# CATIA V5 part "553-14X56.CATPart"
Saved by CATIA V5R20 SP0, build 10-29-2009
Part number: 553-14x56
Definition: NONE
Nomenclature: 553-14x56
Source: Unknown
Description: 553-14x56
Bounding box of the stored display mesh (mm): x 0 to 56, y -12.5 to 12.5, z -12.5 to 12.5
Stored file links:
  C:\Users\Utente\Desktop\IO LAVORO\3D X SITO CF\X SITO\PLASTICA\553\553-14X56.CATPart
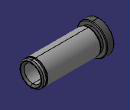
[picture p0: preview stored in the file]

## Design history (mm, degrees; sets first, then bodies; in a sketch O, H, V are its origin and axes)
Body1 "553-14x56" (main body)
  Solid1: solid without history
